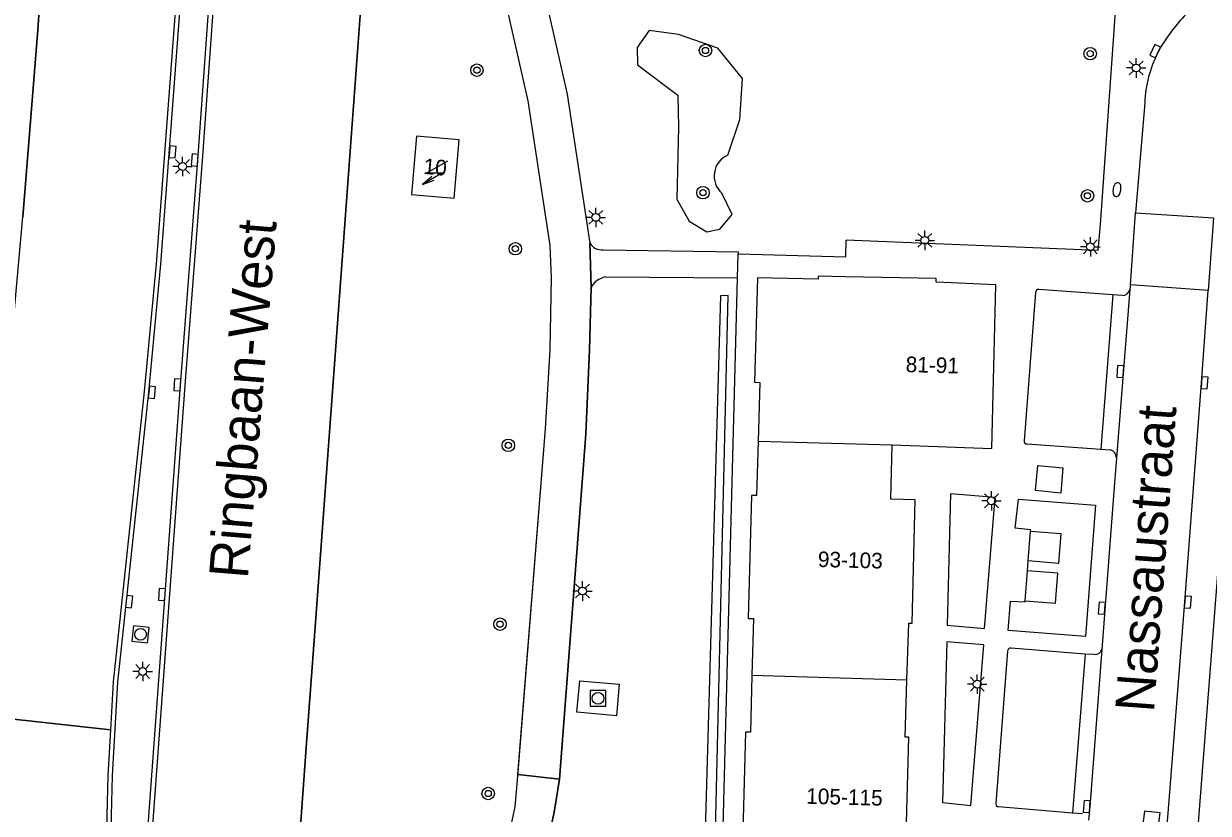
# Model space of a CAD drawing. Extents: x 132573 to 132944, y 398226 to 398676.
# Drawn here: x 132750.7 to 132826.8, y 398387.4 to 398438.1 of the extents above; entities that cross this region are included whole.
import ezdxf

# ---------------------------------------------------------------- set-up
doc = ezdxf.new("R2010")
doc.units = 0
for name, color, linetype in [('gg-anno-huisnummerreeks BGT', 7, 'Continuous'), ('gg-anno-openbare ruimte label', 7, 'Continuous'), ('gg-bbg-hoofdgebouw', 7, 'Continuous'), ('gg-bbg-tussenscheiding', 7, 'Continuous'), ('gg-knt-verharding', 7, 'Continuous'), ('gg-knt-verharding nz', 7, 'Continuous'), ('gg-kwrk-afval apart plaats', 7, 'Continuous'), ('gt-grn-groengrens', 7, 'Continuous'), ('gt-symb-boom', 7, 'Continuous'), ('gt-symb-brandkraan', 7, 'Continuous'), ('gt-symb-kolk', 7, 'Continuous'), ('gt-symb-lichtmast', 7, 'Continuous'), ('gt-symb-rioolschacht', 7, 'Continuous'), ('gt-symb-trafo symbool', 7, 'Continuous'), ('ir-asfa-asfalt arcering', 7, 'Continuous'), ('ir-asfa-asfalt rood', 7, 'Continuous')]:
    doc.layers.add(name, color=color, linetype=linetype)

msp = doc.modelspace()

# ---------------------------------------------------------------- linework, layer by layer
at = {"layer": 'gg-bbg-hoofdgebouw'}
msp.add_line((132806.45, 398411.03), (132812.85, 398410.8), dxfattribs=at)
for points in [[(132778.662, 398430.618), (132775.921, 398430.852), (132775.601, 398427.106), (132778.342, 398426.872), (132778.662, 398430.618)], [(132803.457, 398421.818), (132801.7, 398421.85), (132801.7, 398421.66), (132797.82, 398421.75), (132797.62, 398415.05), (132797.96, 398415.04), (132797.856, 398411.277)], [(132812.85, 398410.8), (132813.12, 398421.31), (132809.29, 398421.48), (132809.29, 398421.71), (132803.457, 398421.818)], [(132797.856, 398411.277), (132797.76, 398407.79), (132797.43, 398407.78), (132797.22, 398399.89), (132797.56, 398399.88), (132797.46, 398396.224)], [(132807.41, 398395.925), (132807.52, 398399.58), (132807.74, 398399.58), (132807.93, 398407.51), (132806.37, 398407.55), (132806.45, 398411.03)], [(132797.46, 398396.224), (132797.36, 398392.58), (132797.05, 398392.59), (132796.83, 398384.66), (132797.17, 398384.65), (132797.05, 398381.18)], [(132807.01, 398380.9), (132807.1, 398384.39), (132807.32, 398384.37), (132807.53, 398392.27), (132807.3, 398392.27), (132807.41, 398395.925)]]:
    msp.add_lwpolyline(points, dxfattribs=at)
at = {"layer": 'gg-bbg-tussenscheiding'}
for p, q in [((132797.856, 398411.277), (132806.45, 398411.03)), ((132807.41, 398395.925), (132797.46, 398396.224))]:
    msp.add_line(p, q, dxfattribs=at)
at = {"layer": 'gg-knt-verharding'}
for p, q in [((132769.392, 398399.047), (132772.884, 398446.484)), ((132823.611, 398436.415), (132823.515, 398436.21)), ((132822.67, 398432.988), (132822.089, 398425.934)), ((132824.644, 398367.756), (132829.363, 398428.64)), ((132821.755, 398421.298), (132822.089, 398425.934)), ((132822.089, 398425.934), (132827.093, 398425.596)), ((132827.093, 398425.596), (132826.738, 398420.929)), ((132803.48, 398423.09), (132803.51, 398424.16)), ((132796.539, 398421.759), (132796.58, 398423.3)), ((132796.58, 398423.3), (132803.48, 398423.09)), ((132788.051, 398421.807), (132796.539, 398421.759)), ((132795.57, 398385.14), (132796.539, 398421.759)), ((132815.666, 398420.816), (132814.933, 398411.279)), ((132820.627, 398420.662), (132815.876, 398421.009)), ((132821.755, 398421.298), (132821.722, 398421.013)), ((132826.738, 398420.929), (132821.755, 398421.298)), ((132821.225, 398420.609), (132820.627, 398420.662)), ((132815.124, 398411.088), (132819.863, 398410.746)), ((132819.863, 398410.746), (132820.452, 398410.703)), ((132820.858, 398410.204), (132820.662, 398407.752)), ((132812.376, 398399.249), (132813.072, 398407.652)), ((132814.349, 398405.686), (132814.574, 398407.538)), ((132820.662, 398407.752), (132819.912, 398397.905)), ((132815.196, 398403.576), (132815.346, 398405.488)), ((132815.147, 398402.943), (132815.196, 398403.576)), ((132814.996, 398401.015), (132815.147, 398402.943)), ((132813.907, 398399.114), (132814.05, 398400.993)), ((132768.845, 398391.611), (132769.392, 398399.047)), ((132809.981, 398399.45), (132812.376, 398399.249)), ((132809.965, 398398.386), (132809.693, 398388.078)), ((132812.344, 398398.185), (132809.965, 398398.386)), ((132811.503, 398387.877), (132812.344, 398398.185)), ((132813.87, 398397.788), (132813.119, 398388.004)), ((132818.85, 398397.602), (132814.101, 398397.99)), ((132819.471, 398397.566), (132818.85, 398397.602)), ((132809.693, 398388.078), (132811.503, 398387.877)), ((132813.294, 398387.808), (132818.043, 398387.401)), ((132818.043, 398387.401), (132818.682, 398387.358))]:
    msp.add_line(p, q, dxfattribs=at)
for points in [[(132784.182, 398484.838), (132781.948, 398453.975), (132782.39, 398448.736), (132783.241, 398443.914), (132785.6, 398433.54), (132787.055, 398423.975)], [(132753.3, 398299.864), (132755.636, 398329.162), (132756.237, 398337.37), (132756.613, 398343.619), (132757.317, 398357.072), (132758.127, 398378.751), (132760.776, 398414.868), (132761.889, 398429.296), (132764.039, 398459.154), (132765.586, 398479.069)], [(132751.083, 398300.042), (132756.534, 398372.062), (132756.626, 398374.274), (132756.591, 398377.31), (132756.41, 398381.327), (132756.304, 398385.531), (132756.415, 398389.799), (132756.753, 398395.79), (132758.744, 398414.418), (132759.507, 398422.619), (132763.174, 398471.173), (132763.665, 398478.479)], [(132769.561, 398303.283), (132769.399, 398307.62), (132769.421, 398308.718), (132770.341, 398314.976), (132771.354, 398325.693), (132772.297, 398336.945), (132773.356, 398347.504), (132774.813, 398357.892), (132777.118, 398367.913), (132780.159, 398378.036), (132782.25, 398387.791), (132782.424, 398389.763), (132784.201, 398412.055), (132784.507, 398417.133), (132784.588, 398421.772), (132784.51, 398423.836), (132783.085, 398433.113), (132780.793, 398443.311), (132779.879, 398448.461), (132779.385, 398453.816)], [(132752.555, 398450.718), (132751.599, 398437.386), (132750.659, 398425.658)], [(132820.924, 398440.982), (132819.807, 398425.182), (132819.656, 398423.517), (132803.51, 398424.16)], [(132787.91, 398423.551), (132796.583, 398423.411), (132796.58, 398423.3)], [(132771.98, 398303.047), (132771.788, 398306.193), (132771.845, 398308.224), (132772.853, 398314.758), (132773.898, 398325.679), (132774.85, 398336.902), (132775.884, 398347.278), (132777.371, 398357.589), (132779.553, 398367.268), (132782.624, 398377.407), (132784.767, 398387.448), (132785.107, 398389.577), (132786.805, 398411.719), (132787.031, 398417.139), (132787.129, 398421.145)], [(132813.072, 398407.652), (132810.205, 398407.877), (132809.981, 398399.45)], [(132814.574, 398407.538), (132819.506, 398407.158), (132818.86, 398398.738), (132813.907, 398399.114)], [(132815.346, 398405.488), (132815.352, 398405.568), (132814.349, 398405.686)], [(132814.05, 398400.993), (132814.991, 398400.952), (132814.996, 398401.015)], [(132788.762, 398393.647), (132786.224, 398393.87), (132786.412, 398395.878), (132788.946, 398395.662), (132788.762, 398393.647)], [(132764.017, 398309.742), (132766.081, 398339.639), (132766.643, 398348.698), (132767.065, 398357.764), (132767.263, 398363.623), (132767.769, 398374.645), (132768.407, 398385.661), (132768.845, 398391.611)]]:
    msp.add_lwpolyline(points, dxfattribs=at)
for centre, radius, start, end in [((132833.836, 398430.429), 11.849, 134.89737, 149.6532), ((132830.46, 398432.667), 7.797, 152.97091, 177.63827), ((132787.837, 398424.478), 0.93, 212.76307, 274.48271), ((132788.318, 398420.462), 1.371, 101.22213, 150.1349), ((132815.871, 398420.804), 0.205, 88.53984, 176.62913), ((132821.217, 398421.126), 0.517, 270.85371, 347.36004), ((132815.106, 398411.261), 0.174, 174.05002, 275.94998), ((132820.336, 398410.194), 0.523, 1.14354, 77.12194), ((132814.08, 398397.78), 0.211, 84.38189, 177.95483), ((132819.463, 398398.033), 0.467, 270.97395, 344.12555), ((132813.295, 398387.985), 0.177, 173.91024, 269.61036)]:
    msp.add_arc(centre, radius, start, end, dxfattribs=at)
at = {"layer": 'gg-knt-verharding nz'}
for p, q in [((132787.129, 398421.145), (132787.055, 398423.975)), ((132821.722, 398421.013), (132820.858, 398410.204)), ((132820.627, 398420.662), (132819.863, 398410.746)), ((132818.85, 398397.602), (132818.043, 398387.401))]:
    msp.add_line(p, q, dxfattribs=at)
for points in [[(132822.678, 398367.717), (132823.197, 398374.914), (132825.235, 398400.952), (132826.312, 398415.022), (132826.738, 398420.929)], [(132819.912, 398397.905), (132819.149, 398387.801), (132819.054, 398386.947)]]:
    msp.add_lwpolyline(points, dxfattribs=at)
at = {"layer": 'gg-kwrk-afval apart plaats'}
for points in [[(132817.415, 398409.553), (132817.279, 398407.937), (132815.661, 398408.097), (132815.813, 398409.697), (132817.415, 398409.553)], [(132815.346, 398405.488), (132817.284, 398405.336), (132817.137, 398403.424), (132815.196, 398403.576)], [(132814.996, 398401.015), (132816.946, 398400.862), (132817.083, 398402.792), (132815.147, 398402.943)]]:
    msp.add_lwpolyline(points, dxfattribs=at)
at = {"layer": 'gt-grn-groengrens'}
for points in [[(132795.914, 398429.629), (132796.674, 398431.917), (132796.843, 398434.541), (132795.265, 398436.504), (132792.754, 398437.367), (132790.872, 398437.619), (132790.091, 398436.538), (132790.116, 398435.423), (132792.696, 398433.47), (132792.739, 398431.422), (132792.643, 398426.799), (132793.436, 398425.383), (132794.555, 398424.707), (132795.404, 398424.881), (132796.199, 398425.812), (132795.53, 398427.187)], [(132795.09, 398385.365), (132795.925, 398420.614), (132795.446, 398420.602), (132794.432, 398385.527)]]:
    msp.add_lwpolyline(points, dxfattribs=at)
msp.add_arc((132796.489, 398428.287), 1.459, 113.18417, 228.94288, dxfattribs=at)
at = {"layer": 'gt-symb-boom'}
for centre, radius in [((132794.479, 398436.343), 0.4), ((132794.479, 398436.343), 0.2), ((132819.171, 398436.144), 0.4), ((132819.171, 398436.144), 0.2), ((132779.805, 398435.084), 0.4), ((132779.805, 398435.084), 0.2), ((132794.313, 398427.214), 0.4), ((132794.313, 398427.214), 0.2), ((132818.995, 398427.018), 0.4), ((132818.995, 398427.018), 0.2), ((132782.276, 398423.618), 0.4), ((132782.276, 398423.618), 0.2), ((132781.825, 398410.996), 0.4), ((132781.825, 398410.996), 0.2), ((132781.284, 398399.521), 0.4), ((132781.284, 398399.521), 0.2), ((132780.53, 398388.649), 0.4), ((132780.53, 398388.649), 0.2)]:
    msp.add_circle(centre, radius, dxfattribs=at)
at = {"layer": 'gt-symb-brandkraan'}
for centre, radius, start, end in [((132821.571, 398427.302), 0.938, 154.11395, 187.89804), ((132823.427, 398426.402), 3, 153.43905, 154.11395), ((132820.927, 398427.651), 0.206, 8.57292, 153.43905), ((132820.207, 398427.518), 0.938, 334.11397, 7.89802), ((132818.164, 398427.235), 3, 7.89802, 8.57292), ((132823.614, 398427.585), 3, 187.89804, 188.57293), ((132820.851, 398427.169), 0.206, 188.57293, 333.43907), ((132818.351, 398428.418), 3, 333.43907, 334.11397)]:
    msp.add_arc(centre, radius, start, end, dxfattribs=at)
at = {"layer": 'gt-symb-kolk'}
for points in [[(132823.515, 398436.21), (132823.674, 398436.55), (132823.312, 398436.719), (132822.994, 398436.04), (132823.356, 398435.87), (132823.515, 398436.21)], [(132760.065, 398429.848), (132760.036, 398429.474), (132760.435, 398429.444), (132760.492, 398430.192), (132760.094, 398430.222), (132760.065, 398429.848)], [(132761.889, 398429.296), (132761.918, 398429.67), (132761.519, 398429.701), (132761.461, 398428.953), (132761.86, 398428.922), (132761.889, 398429.296)], [(132821.3, 398415.719), (132821.33, 398416.093), (132820.931, 398416.125), (132820.871, 398415.377), (132821.27, 398415.345), (132821.3, 398415.719)], [(132758.744, 398414.418), (132758.708, 398414.045), (132759.106, 398414.006), (132759.178, 398414.753), (132758.78, 398414.791), (132758.744, 398414.418)], [(132760.776, 398414.868), (132760.803, 398415.242), (132760.404, 398415.271), (132760.35, 398414.523), (132760.749, 398414.494), (132760.776, 398414.868)], [(132826.312, 398415.022), (132826.283, 398414.648), (132826.682, 398414.618), (132826.739, 398415.365), (132826.341, 398415.396), (132826.312, 398415.022)], [(132759.787, 398401.404), (132759.814, 398401.778), (132759.415, 398401.807), (132759.361, 398401.059), (132759.76, 398401.03), (132759.787, 398401.404)], [(132757.284, 398400.992), (132757.243, 398400.619), (132757.641, 398400.576), (132757.722, 398401.322), (132757.325, 398401.365), (132757.284, 398400.992)], [(132825.235, 398400.952), (132825.206, 398400.578), (132825.605, 398400.547), (132825.663, 398401.295), (132825.264, 398401.326), (132825.235, 398400.952)], [(132820.119, 398400.536), (132820.147, 398400.91), (132819.748, 398400.94), (132819.692, 398400.192), (132820.091, 398400.162), (132820.119, 398400.536)], [(132819.149, 398387.801), (132819.177, 398388.175), (132818.778, 398388.205), (132818.722, 398387.457), (132819.121, 398387.427), (132819.149, 398387.801)]]:
    msp.add_lwpolyline(points, dxfattribs=at)
at = {"layer": 'gt-symb-lichtmast'}
for p, q in [((132821.942, 398435.401), (132821.677, 398435.666)), ((132822.119, 398435.474), (132822.119, 398435.849)), ((132822.296, 398435.401), (132822.561, 398435.666)), ((132821.869, 398435.224), (132821.494, 398435.224)), ((132821.942, 398435.047), (132821.677, 398434.782)), ((132822.119, 398434.974), (132822.119, 398434.599)), ((132822.561, 398434.782), (132822.296, 398435.047)), ((132822.369, 398435.224), (132822.744, 398435.224)), ((132760.732, 398429.076), (132760.467, 398429.341)), ((132760.909, 398429.149), (132760.909, 398429.524)), ((132761.086, 398429.076), (132761.351, 398429.341)), ((132760.659, 398428.899), (132760.284, 398428.899)), ((132760.732, 398428.722), (132760.467, 398428.457)), ((132760.909, 398428.649), (132760.909, 398428.274)), ((132761.351, 398428.457), (132761.086, 398428.722)), ((132761.159, 398428.899), (132761.534, 398428.899)), ((132787.439, 398425.88), (132787.439, 398426.255)), ((132787.189, 398425.63), (132786.814, 398425.63)), ((132787.262, 398425.807), (132786.997, 398426.072)), ((132787.262, 398425.453), (132786.997, 398425.188)), ((132787.439, 398425.38), (132787.439, 398425.005)), ((132787.616, 398425.807), (132787.881, 398426.072)), ((132787.881, 398425.188), (132787.616, 398425.453)), ((132787.689, 398425.63), (132788.064, 398425.63)), ((132808.559, 398424.405), (132808.559, 398424.78)), ((132808.309, 398424.155), (132807.934, 398424.155)), ((132808.382, 398424.332), (132808.117, 398424.597)), ((132808.382, 398423.978), (132808.117, 398423.713)), ((132808.559, 398423.905), (132808.559, 398423.53)), ((132808.736, 398424.332), (132809.001, 398424.597)), ((132809.001, 398423.713), (132808.736, 398423.978)), ((132808.809, 398424.155), (132809.184, 398424.155)), ((132819.003, 398423.921), (132818.738, 398424.186)), ((132819.18, 398423.994), (132819.18, 398424.369)), ((132819.357, 398423.921), (132819.622, 398424.186)), ((132818.93, 398423.744), (132818.555, 398423.744)), ((132819.003, 398423.567), (132818.738, 398423.302)), ((132819.18, 398423.494), (132819.18, 398423.119)), ((132819.622, 398423.302), (132819.357, 398423.567)), ((132819.43, 398423.744), (132819.805, 398423.744)), ((132812.657, 398407.616), (132812.392, 398407.881)), ((132812.834, 398407.689), (132812.834, 398408.064)), ((132813.011, 398407.616), (132813.276, 398407.881)), ((132812.584, 398407.439), (132812.209, 398407.439)), ((132812.657, 398407.262), (132812.392, 398406.997)), ((132812.834, 398407.189), (132812.834, 398406.814)), ((132813.276, 398406.997), (132813.011, 398407.262)), ((132813.084, 398407.439), (132813.459, 398407.439)), ((132786.406, 398401.824), (132786.141, 398402.089)), ((132786.583, 398401.897), (132786.583, 398402.272)), ((132786.76, 398401.824), (132787.025, 398402.089)), ((132786.333, 398401.647), (132785.958, 398401.647)), ((132786.406, 398401.47), (132786.141, 398401.205)), ((132786.583, 398401.397), (132786.583, 398401.022)), ((132787.025, 398401.205), (132786.76, 398401.47)), ((132786.833, 398401.647), (132787.208, 398401.647)), ((132758.103, 398396.48), (132757.728, 398396.48)), ((132758.176, 398396.657), (132757.911, 398396.922)), ((132758.353, 398396.73), (132758.353, 398397.105)), ((132758.53, 398396.657), (132758.795, 398396.922)), ((132758.603, 398396.48), (132758.978, 398396.48)), ((132758.176, 398396.303), (132757.911, 398396.038)), ((132758.353, 398396.23), (132758.353, 398395.855)), ((132758.795, 398396.038), (132758.53, 398396.303)), ((132811.742, 398395.847), (132811.477, 398396.112)), ((132811.919, 398395.92), (132811.919, 398396.295)), ((132812.096, 398395.847), (132812.361, 398396.112)), ((132811.669, 398395.67), (132811.294, 398395.67)), ((132811.742, 398395.493), (132811.477, 398395.228)), ((132811.919, 398395.42), (132811.919, 398395.045)), ((132812.361, 398395.228), (132812.096, 398395.493)), ((132812.169, 398395.67), (132812.544, 398395.67))]:
    msp.add_line(p, q, dxfattribs=at)
for centre in [(132822.119, 398435.224), (132760.909, 398428.899), (132787.439, 398425.63), (132808.559, 398424.155), (132819.18, 398423.744), (132812.834, 398407.439), (132786.583, 398401.647), (132758.353, 398396.48), (132811.919, 398395.67)]:
    msp.add_circle(centre, 0.25, dxfattribs=at)
at = {"layer": 'gt-symb-rioolschacht'}
for points in [[(132757.665, 398398.425), (132758.66, 398398.322), (132758.763, 398399.317), (132757.768, 398399.42)], [(132787.079, 398394.259), (132788.079, 398394.259), (132788.079, 398395.259), (132787.079, 398395.259)], [(132823.53, 398386.408), (132823.655, 398387.401), (132822.662, 398387.526), (132822.537, 398386.533)]]:
    msp.add_lwpolyline(points, close=True, dxfattribs=at)
for centre in [(132758.214, 398398.871), (132787.579, 398394.759)]:
    msp.add_circle(centre, 0.375, dxfattribs=at)
at = {"layer": 'gt-symb-trafo symbool'}
for points in [[(132777.907, 398429.243), (132776.607, 398428.493), (132777.607, 398428.493), (132776.307, 398427.743)], [(132776.919, 398428.257), (132776.307, 398427.743), (132777.059, 398428.017)]]:
    msp.add_lwpolyline(points, dxfattribs=at)
at = {"layer": 'ir-asfa-asfalt arcering'}
for points in [[(132762.875, 398471.194), (132759.208, 398422.644), (132758.445, 398414.448), (132756.454, 398395.814), (132756.281, 398392.746), (132747.325, 398393.731), (132747.607, 398395.706), (132748.578, 398403.587), (132748.835, 398405.92), (132748.964, 398405.91), (132749.5, 398412.772), (132750.659, 398425.658), (132751.599, 398437.386), (132752.555, 398450.718)], [(132756.536, 398337.35), (132756.913, 398343.602), (132757.617, 398357.059), (132758.427, 398378.734), (132761.075, 398414.845), (132762.188, 398429.274), (132764.338, 398459.132)], [(132772.884, 398446.484), (132769.392, 398399.047), (132768.845, 398391.611), (132768.407, 398385.661), (132767.769, 398374.645), (132767.263, 398363.623), (132767.065, 398357.764), (132766.643, 398348.698), (132766.081, 398339.639)], [(132745.571, 398382.431), (132746.483, 398387.846), (132747.325, 398393.731), (132756.281, 398392.746), (132756.115, 398389.811), (132756.004, 398385.531), (132756.11, 398381.316), (132756.291, 398377.302), (132756.326, 398374.279), (132756.234, 398372.08), (132750.784, 398300.065), (132750.784, 398300.061), (132750.599, 398297.174), (132750.599, 398297.173), (132737.591, 398297.947)]]:
    msp.add_lwpolyline(points, dxfattribs=at)
at = {"layer": 'ir-asfa-asfalt rood'}
msp.add_lwpolyline([(132784.201, 398412.055), (132784.507, 398417.133), (132784.588, 398421.772), (132784.51, 398423.836), (132783.085, 398433.113), (132780.793, 398443.311), (132779.879, 398448.461), (132779.385, 398453.816), (132779.482, 398455.792), (132779.956, 398462.528), (132780.649, 398470.778), (132781.787, 398484.679), (132784.187, 398484.912), (132784.182, 398484.838), (132781.948, 398453.975), (132782.39, 398448.736), (132783.241, 398443.914), (132785.6, 398433.54), (132787.055, 398423.975), (132787.129, 398421.145), (132787.031, 398417.139), (132786.805, 398411.719), (132785.107, 398389.577), (132782.433, 398389.871)], close=True, dxfattribs=at)
msp.add_lwpolyline([(132772.297, 398336.945), (132773.356, 398347.504), (132774.813, 398357.892), (132777.118, 398367.913), (132780.159, 398378.036), (132782.25, 398387.791), (132782.424, 398389.763), (132782.433, 398389.871), (132785.107, 398389.577), (132784.767, 398387.448), (132782.624, 398377.407), (132779.553, 398367.268), (132777.371, 398357.589), (132775.884, 398347.278), (132774.85, 398336.902)], dxfattribs=at)

# ---------------------------------------------------------------- texts
at = {"layer": 'gg-anno-huisnummerreeks BGT'}
for s, rotation, p in [('10', 355.1, (132776.348, 398428.427)), ('81-91', 358.5, (132807.316, 398415.704)), ('93-103', 358.6, (132801.682, 398403.193)), ('105-115', 358.5, (132800.932, 398387.995))]:
    msp.add_text(s, height=1, rotation=rotation, dxfattribs=at).set_placement(p)
at = {"layer": 'gg-anno-openbare ruimte label'}
for s, rotation, p in [('Ringbaan-West', 85.4, (132765.098, 398402.393)), ('Nassaustraat', 85.8, (132823.262, 398393.817))]:
    msp.add_text(s, height=2.5, rotation=rotation, dxfattribs=at).set_placement(p)

doc.saveas('drawing.dxf')
